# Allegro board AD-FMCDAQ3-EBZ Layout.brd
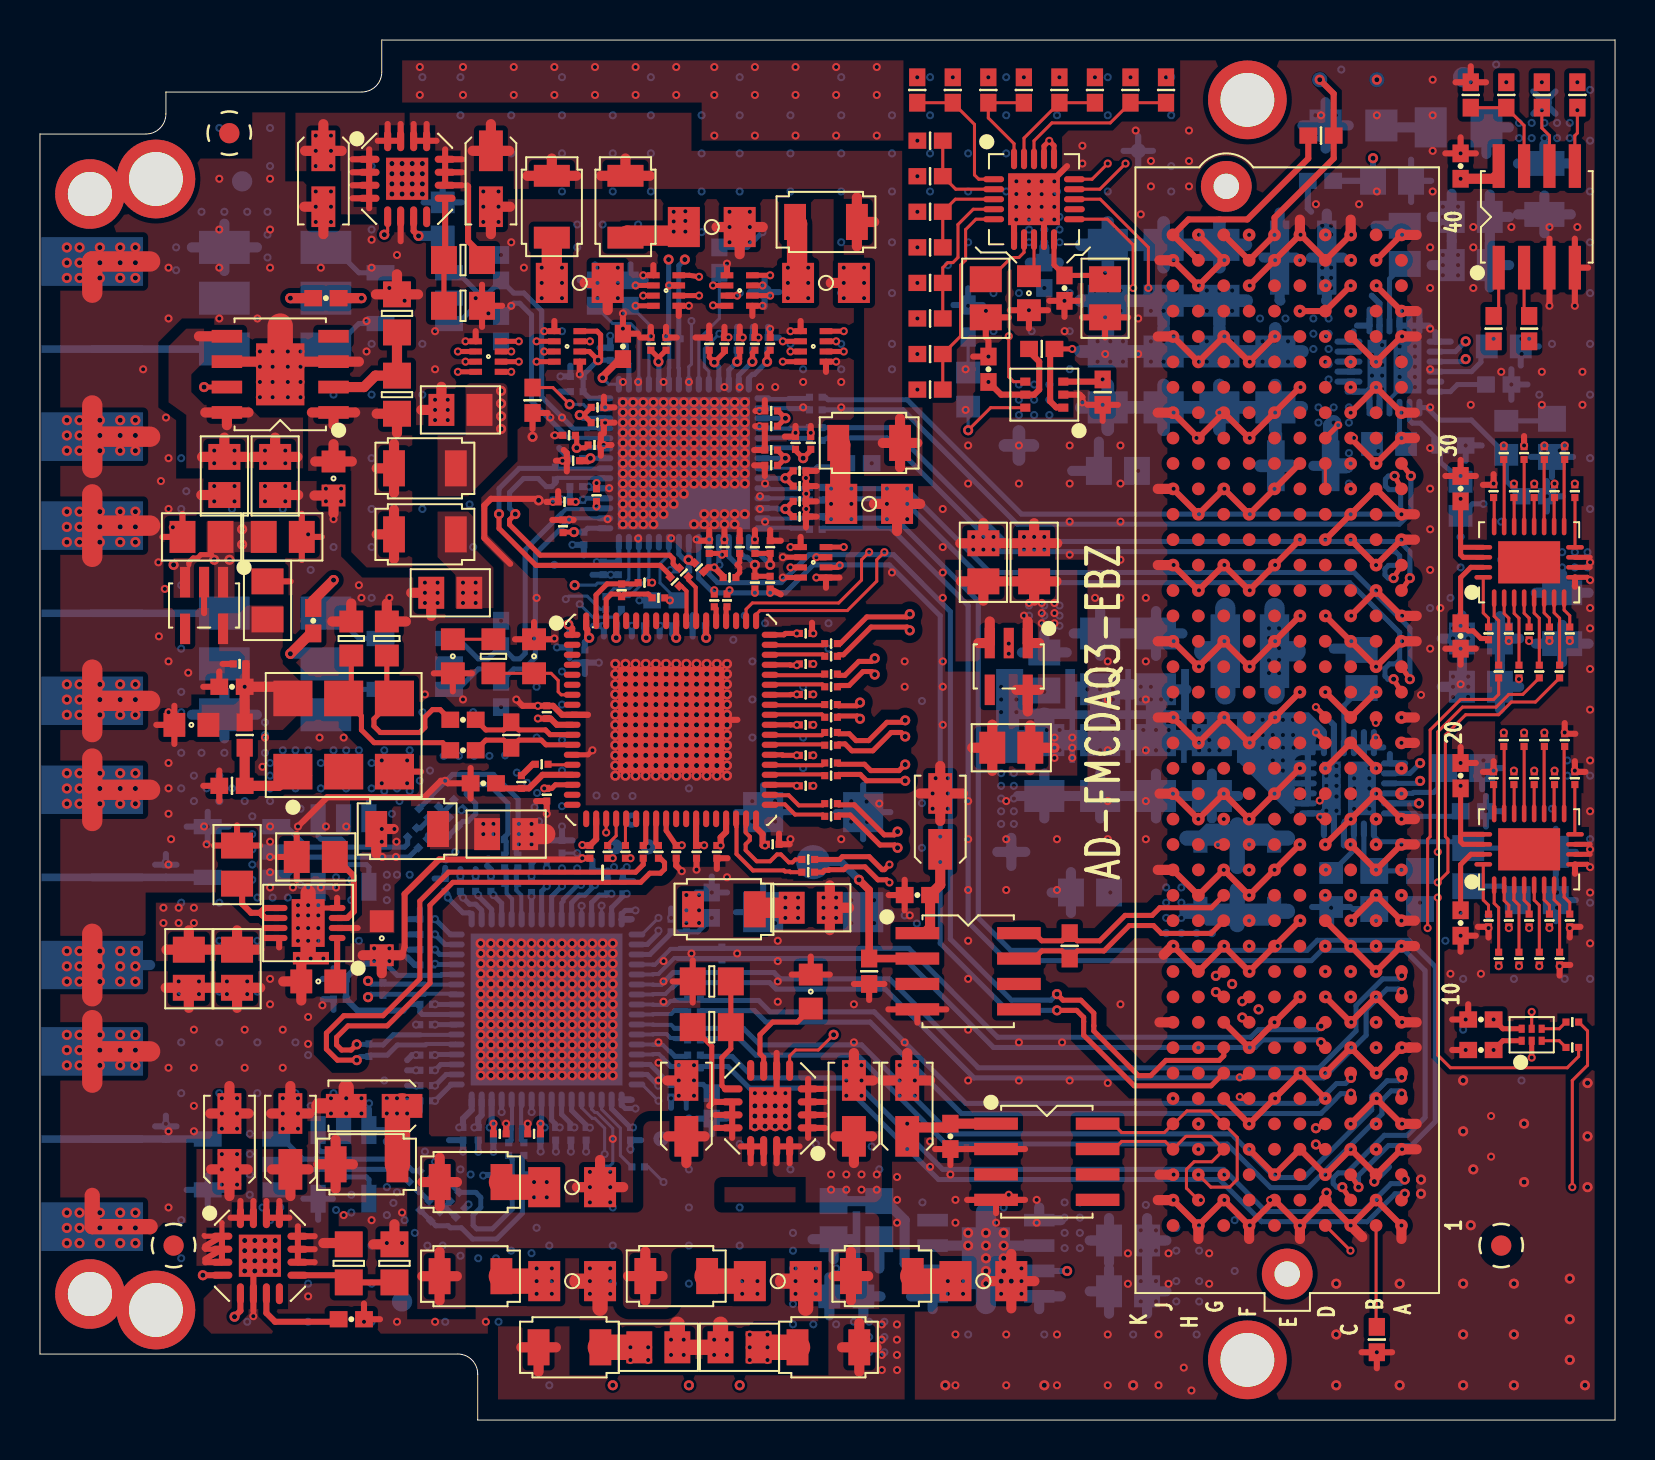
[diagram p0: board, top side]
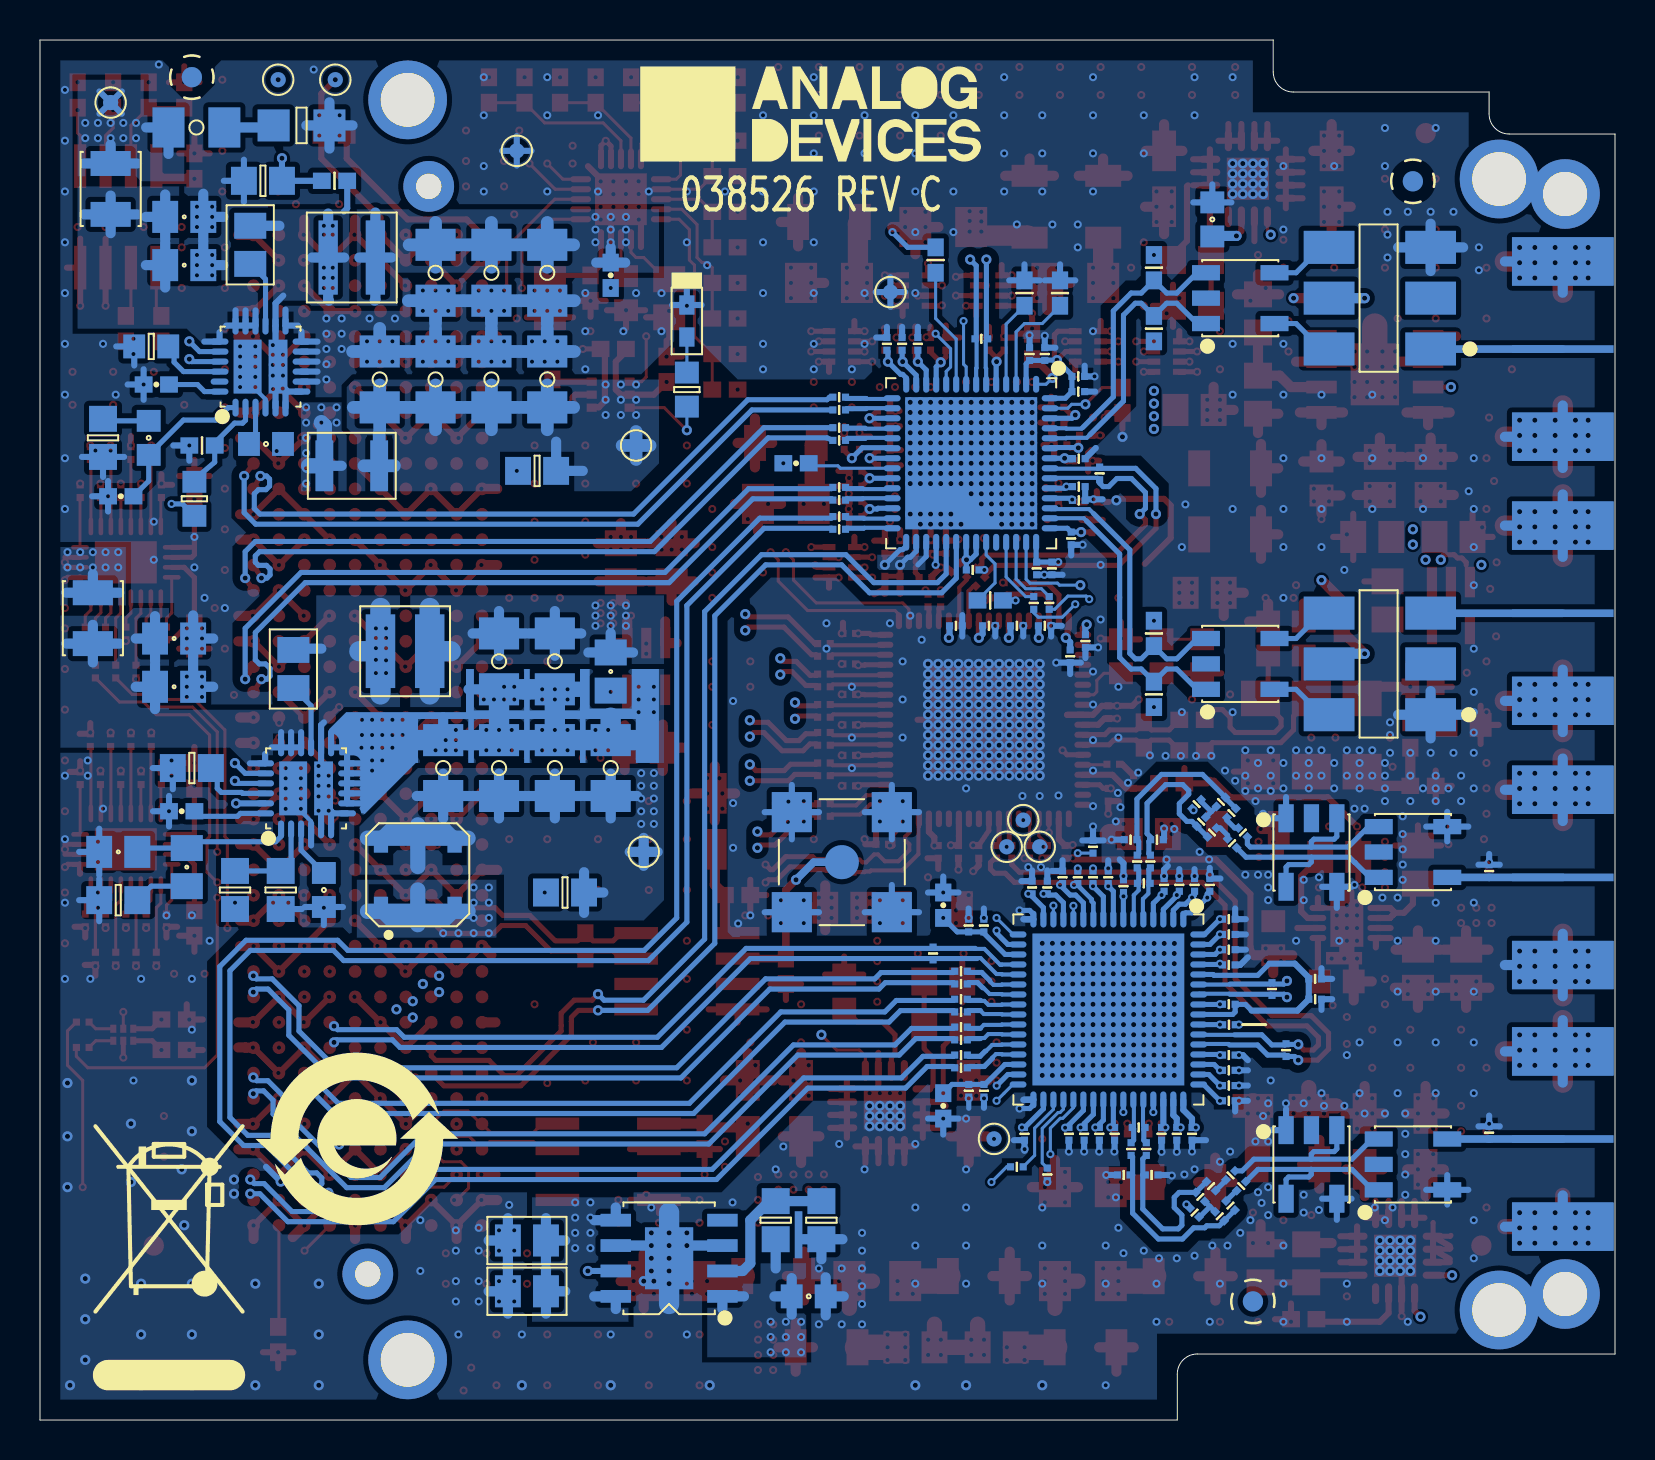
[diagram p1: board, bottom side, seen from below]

Outline 78.8 x 69 mm; copper layers: TOP, L2_AGND, L3_SIG, L4_AGND, L5_PWR, L6_PWR, L7_AGND, L8_SIG, L9_AGND, BOTTOM. Coordinates in mm from the lower left corner of the outline.
Outline path: 0,64.3 0,3.3 20.9,3.3 arc(21.61,3.01) 21.9,2.3 21.9,0 78.8,0 78.8,69 17.1,69 17.1,67.4 arc(16.81,66.69) 16.1,66.4 6.3,66.4 6.3,65.3 arc(6.01,64.59) 5.3,64.3 0,64.3

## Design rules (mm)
constraint set DEFAULT: min track width 0.152
net group ADC_CLK: nets ADC_CLK_N ADC_CLK_P
net group ADC_CLK1: nets ADC_CLK1_N ADC_CLK1_P
net group ADC_CLK_FMC: nets ADC_CLK_FMC_N ADC_CLK_FMC_P
net group ADC_CLK_FMC1: nets ADC_CLK_FMC1_N ADC_CLK_FMC1_P
net group ADC_SYNC: nets ADC_SYNC_N ADC_SYNC_P
net group ADC_SYSREF: nets ADC_SYSREF_N ADC_SYSREF_P
net group ADC_SYSREF1: nets ADC_SYSREF1_N ADC_SYSREF1_P
net group CLKD_SYSREF_ADC: nets CLKD_SYSREF_ADC_N CLKD_SYSREF_ADC_P
net group CLKD_SYSREF_ADC1: nets CLKD_SYSREF_ADC1_N CLKD_SYSREF_ADC1_P
net group CLKD_SYSREF_DAC: nets CLKD_SYSREF_DAC_N CLKD_SYSREF_DAC_P
net group CLKD_SYSREF_DAC1: nets CLKD_SYSREF_DAC1_N CLKD_SYSREF_DAC1_P
net group CLKEXT_TRIG: nets EXT_TRIG_N EXT_TRIG_P
net group CLKVINA: nets VINA_N VINA_P
net group CLKVINB: nets VINB_N VINB_P
net group DAC_CLK_FMC: nets DAC_CLK_FMC_N DAC_CLK_FMC_P
net group DAC_CLK_FMC1: nets DAC_CLK_FMC1_N DAC_CLK_FMC1_P
net group DAC_CLK_N: nets DAC_CLK1_N DAC_CLK_N
net group DAC_CLK_P: nets DAC_CLK1_P DAC_CLK_P
net group DAC_SYNC: nets DAC_SYNC_N DAC_SYNC_P
net group DAC_SYSREF: nets DAC_SYSREF_N DAC_SYSREF_P
net group DAC_SYSREF1: nets DAC_SYSREF1_N DAC_SYSREF1_P
net group DP2: nets UNNAMED_4_CAP_I87_N1 UNNAMED_4_CAP_I90_N1
net group DP3: nets UNNAMED_5_CAP_I52_N2 UNNAMED_5_CAP_I53_N2
net group DP4: nets UNNAMED_4_CAP_I87_N2 UNNAMED_4_CAP_I90_N2
net group DP6: nets UNNAMED_4_AD9528_I220_OUT3 UNNAMED_4_AD9528_I220_OUT3N
net group FMC_SERDIN0: nets DAC_SERDIN0_N DAC_SERDIN0_P
net group FMC_SERDIN0_A: nets FMC_SERDIN0_N FMC_SERDIN0_P
net group FMC_SERDIN1: nets DAC_SERDIN1_N DAC_SERDIN1_P
net group FMC_SERDIN1_A: nets FMC_SERDIN1_N FMC_SERDIN1_P
net group FMC_SERDIN2: nets DAC_SERDIN2_N DAC_SERDIN2_P
net group FMC_SERDIN2_A: nets FMC_SERDIN2_N FMC_SERDIN2_P
net group FMC_SERDIN3: nets DAC_SERDIN3_N DAC_SERDIN3_P
net group FMC_SERDIN3_A: nets FMC_SERDIN3_N FMC_SERDIN3_P
net group FMC_SERDOUT0: nets ADC_SERDOUT0_N ADC_SERDOUT0_P
net group FMC_SERDOUT0_A: nets FMC_SERDOUT0_N FMC_SERDOUT0_P
net group FMC_SERDOUT1: nets ADC_SERDOUT1_N ADC_SERDOUT1_P
net group FMC_SERDOUT1_A: nets FMC_SERDOUT1_N FMC_SERDOUT1_P
net group FMC_SERDOUT2: nets ADC_SERDOUT2_N ADC_SERDOUT2_P
net group FMC_SERDOUT2_A: nets FMC_SERDOUT2_N FMC_SERDOUT2_P
net group FMC_SERDOUT3: nets ADC_SERDOUT3_N ADC_SERDOUT3_P
net group FMC_SERDOUT3_A: nets FMC_SERDOUT3_N FMC_SERDOUT3_P
net group OUT0: nets OUT0_N OUT0_P
net group OUT1: nets OUT1_N OUT1_P
net group SYSREF: nets FMC_SYSREF_N FMC_SYSREF_P
net group SYSREF_A: nets FMC_SYSREF_N_A FMC_SYSREF_P_A
nets with their own width: min track width 0.254; nets 3P3_SUP ADC_1P2_AVDD ADC_1P2_AVDD_SR ADC_1P2_DRVDD ADC_1P2_DVDD ADC_2P5_AVDD ADC_3P3_AVDD ADC_3P3_SPIVDD DAC_1P2_CVDD12 DAC_1P2_DVDD12 DAC_1P2_PVDD12 DAC_1P2_SVDD12 DAC_3P3_AVDD33 DAC_3P3_IOVDD33 FMC_3P3V FMC_3P3VAUX FMC_12P0V
nets with their own width: min track width 0.508; nets P3V6

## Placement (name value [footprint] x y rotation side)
ADC_CSB  TESTPAD  [TPSMC30]  31.07 14.06 180 bottom
C1  0.1uF  [C0201]  31.76 41.92 135 top
C2  180pF  [C0603]  24.72 38.19 90 top
C3  0.1uF  [C0201]  32.21 42.38 135 top
C4  1uF  [C0603]  20.15 60.03 270 bottom
C5  0.047uF  [C0508IDC]  35.01 56.47 90 top
C6  0.001uF  [C0201]  35.67 53.81 270 bottom
C7  0.047uF  [C0508IDC]  31.32 56.47 270 top
C8  0.1uF  [C0201]  32.72 21.8 180 bottom
C9  0.047uF  [C0508IDC]  26.37 53.68 90 top
C10  0.047uF  [C0508IDC]  38.69 53.68 90 top
C11  0.1uF  [C0201]  39.58 34.38 0 top
C12  0.047uF  [C0508IDC]  38.69 42.88 270 top
C13  10uF  [C0603]  14.69 47.08 270 top
C14  0.1uF  [C0201]  39.58 37.3 0 top
C15  0.1uF  [C0201]  39.58 32.22 0 top
C16  0.1uF  [C0201]  39.58 33.74 0 top
C17  0.1uF  [C0201]  39.58 35.14 0 top
C18  1uF  [C0805H53]  54.44 6.44 0 bottom
C19  0.1uF  [C0201]  39.58 36.66 0 top
C20  0.1uF  [C0201]  32.72 22.44 180 bottom
C21  0.1uF  [C0201]  39.58 35.77 0 top
C22  0.1uF  [C0201]  35.77 53.81 270 top
C23  1uF  [C0805H53]  23.32 29.3 0 top
C24  1uF  [C0805H53]  38.56 25.61 0 top
C25  0.1uF  [C0402]  45.55 14.18 270 top
C26  0.001uF  [C0201]  38 45.93 180 top
C27  10uF  [C0603]  17.1 24.09 270 top
C28  0.1uF  [C0402]  43.9 26.25 180 top
C29  0.1uF  [C0201]  31.32 53.81 270 top
C30  0.1uF  [C0201]  28.53 39.71 0 bottom
C31  4.7uF  [C3216]  9.48 13.93 90 top
C32  0.1uF  [C0201]  32.97 39.71 0 bottom
C33  0.1uF  [C0201]  36.53 41.87 90 top
C34  1uF  [C0805H53]  11.77 47.2 270 top
C35  0.1uF  [C0201]  28.53 53.3 270 bottom
C36  0.001uF  [C0201]  36.58 47.74 0 top
C37  0.1uF  [C0201]  35.01 53.81 270 top
C38  0.001uF  [C0201]  26.83 46.67 0 bottom
C39  1uF  [C0402]  40.98 47.84 0 bottom
C40  0.1uF  [C0201]  30.94 28.41 270 top
C41  0.1uF  [C0201]  30.18 28.41 270 top
C42  0.1uF  [C0402]  14.31 56.09 180 top
C43  0.001uF  [C0201]  35.77 41.87 90 top
C44  0.1uF  [C0402]  13.67 39.96 270 top
C45  10uF  [C0603]  40.34 6.18 180 bottom
C46  0.1uF  [C0201]  27.89 50.63 180 top
C47  0.001uF  [C0201]  38 47.46 180 top
C48  1uF  [C0805H53]  9.23 47.2 270 top
C49  0.1uF  [C0201]  36.58 48.5 0 top
C50  0.1uF  [C0201]  38.56 48.85 270 top
C51  0.001uF  [C0201]  27.21 44.08 90 bottom
C52  0.1uF  [C0201]  36.58 49.69 0 top
C53  0.001uF  [C0201]  30.56 53.81 270 top
C54  0.001uF  [C0201]  37.8 48.85 270 top
C55  0.001uF  [C0201]  36.58 50.45 0 top
C56  0.001uF  [C0201]  36.43 53.81 270 bottom
C57  0.1uF  [C0201]  34.24 43.65 270 top
C58  0.001uF  [C0201]  33.48 43.65 270 top
C59  0.1uF  [C0201]  38.31 39.33 180 top
C60  0.1uF  [C0201]  26.5 38.95 90 bottom
C61  1uF  [C0603]  20.66 38.19 270 top
C62  0.001uF  [C0201]  24.08 31.9 90 top
C63  0.1uF  [C0201]  38.31 33.23 180 top
C64  0.1uF  [C0201]  27.51 28.41 90 top
C65  0.1uF  [C0201]  36.66 28.79 180 top
C66  0.1uF  [C0201]  38.31 31.71 180 top
C67  0.1uF  [C0402]  71.07 62.7 90 top
C68  4.7uF  [C3216]  43.39 15.58 90 top
C69  0.1uF  [C0402]  47.45 52.54 90 top
C70  0.1uF  [C0201]  31.83 28.41 90 top
C71  0.1uF  [C0201]  25.35 35.39 270 top
C72  0.1uF  [C0201]  32.85 28.41 90 top
C73  0.1uF  [C0201]  27.26 38.19 90 bottom
C74  390pF  [C0402]  21.16 35.01 0 top
C75  390pF  [C0402]  21.16 33.49 0 top
C76  4.7uF  [C3216]  45.04 29.93 90 top
C77  0.1uF  [C0201]  33.86 28.41 90 top
C78  0.1uF  [C0201]  29.93 39.71 0 bottom
C79  0.1uF  [C0201]  31.32 39.71 0 bottom
C80  0.1uF  [C0201]  38.31 37.8 180 top
C81  0.1uF  [C0201]  25.35 31.26 90 top
C82  0.1uF  [C0201]  38.31 36.28 180 top
C83  0.1uF  [C0201]  38.31 34.76 180 top
C84  0.1uF  [C0201]  32.72 20.41 180 bottom
C85  0.1uF  [C0201]  32.72 21.04 180 bottom
C86  0.1uF  [C0201]  32.72 19.01 180 bottom
C87  0.1uF  [C0201]  32.72 19.64 180 bottom
C88  0.1uF  [C0201]  32.72 17.61 180 bottom
C89  0.1uF  [C0402]  72.09 18.5 180 top
C90  0.1uF  [C0201]  27.84 46.24 90 top
C91  0.1uF  [C0402]  72.09 20.02 180 top
C92  0.1uF  [C0201]  32.72 18.25 180 bottom
C93  0.1uF  [C0201]  38.82 51.14 180 bottom
C94  0.1uF  [C0201]  35.77 43.65 270 top
C95  0.1uF  [C0201]  38.82 50.5 180 bottom
C96  4.7uF  [C3216]  16.72 15.71 180 top
C97  0.1uF  [C0201]  26.68 47.96 0 top
C98  0.1uF  [C0201]  32.97 42.63 135 top
C99  0.1uF  [C0201]  38.82 49.62 180 bottom
C100  0.1uF  [C0201]  26.12 28.66 90 bottom
C101  0.1uF  [C0201]  34.5 42.12 0 top
C102  0.1uF  [C0201]  38.82 48.98 180 bottom
C103  0.47uF  [C0402]  22.18 31.84 180 top
C104  0.001uF  [C0201]  29.29 53.3 270 bottom
C105  4pF  [C0201]  24.24 29.02 180 bottom
C106  1uF  [C0805H53]  12.15 44.15 0 top
C107  0.1uF  [C0201]  20.93 30.79 135 bottom
C108  0.1uF  [C0201]  18.62 29.38 45 bottom
C109  0.001uF  [C0201]  35.01 43.65 270 top
C110  0.1uF  [C0201]  38.82 46 180 bottom
C111  0.1uF  [C0201]  38.82 46.63 180 bottom
C112  1uF  [C0805H53]  8.08 44.15 180 top
C113  0.001uF  [C0201]  26.85 51.42 0 bottom
C114  0.001uF  [C0201]  32.14 42.5 0 bottom
C115  4pF  [C0201]  23.18 12.25 0 bottom
C116  4pF  [C0201]  24.58 12.25 0 bottom
C117  0.001uF  [C0201]  34.88 53.81 270 bottom
C118  0.1uF  [C0201]  19.24 12.23 315 bottom
C119  1uF  [C0805H53]  11.38 40.98 90 top
C120  0.1uF  [C0201]  26.85 52.18 0 bottom
C121  0.1uF  [C0201]  34.24 53.81 270 top
C122  0.1uF  [C0201]  36.53 53.81 270 top
C123  0.1uF  [C0201]  25.35 27.14 90 bottom
C124  0.1uF  [C0201]  38.82 44.54 180 bottom
C125  0.1uF  [C0201]  27.64 27.14 90 bottom
C126  0.01uF  [C0201]  9.99 37.8 180 top
C127  0.001uF  [C0201]  26.83 48.07 0 bottom
C128  0.001uF  [C0201]  33.48 53.81 270 top
C129  0.1uF  [C0201]  25.04 14.31 270 bottom
C130  0.1uF  [C0201]  22.69 14.31 270 bottom
C131  0.1uF  [C0201]  19.32 16.72 180 bottom
C132  0.1uF  [C0201]  38.82 45.17 180 bottom
C133  0.1uF  [C0201]  19.32 23.52 180 bottom
C134  0.1uF  [C0201]  19.32 24.28 180 bottom
C135  0.1uF  [C0201]  21.04 26.76 90 bottom
C136  0.1uF  [C0201]  21.93 14.31 270 bottom
C137  0.1uF  [C0201]  19.32 18.25 180 bottom
C138  0.1uF  [C0201]  19.32 19.76 180 bottom
C139  0.1uF  [C0201]  19.32 22.75 180 bottom
C140  0.1uF  [C0201]  22.56 26.76 90 bottom
C141  0.1uF  [C0201]  24.59 26.69 90 bottom
C142  0.1uF  [C0201]  24.72 14.31 180 top
C143  0.1uF  [C0201]  23 14.31 0 top
C144  0.1uF  [C0201]  20.27 26.76 90 bottom
C145  0.1uF  [C0201]  21.16 14.31 270 bottom
C146  0.1uF  [C0201]  19.32 15.96 180 bottom
C147  0.1uF  [C0201]  19.32 25.04 180 bottom
C148  0.001uF  [C0402]  15.58 5.04 0 top
C149  1uF  [C0805H53]  9.86 22.56 270 top
C150  0.1uF  [C0201]  28.4 26.63 90 bottom
C151  0.1uF  [C0201]  27.32 14.31 270 bottom
C152  1uF  [C0805H53]  54.44 8.98 0 bottom
C153  0.1uF  [C0201]  29.55 14.31 270 bottom
C154  0.1uF  [C0201]  19.32 20.79 180 bottom
C155  1uF  [C0402]  33.61 25.74 90 bottom
C156  0.1uF  [C0201]  26.17 44.69 270 top
C157  0.1uF  [C0201]  26.24 45.91 0 top
C158  0.001uF  [C0201]  26.83 45.98 0 bottom
C159  0.001uF  [C0201]  26.47 49.23 0 top
C160  0.1uF  [C0201]  27.74 48.75 180 top
C161  0.001uF  [C0201]  27.89 49.87 180 top
C162  0.1uF  [C0201]  39.58 38.19 0 top
C163  1uF  [C0805H53]  47.2 42.88 90 top
C164  1uF  [C0805H53]  21.04 50.5 180 top
C165  1uF  [C0805H53]  13.8 28.15 180 top
C166  1uF  [C0805H53]  7.45 22.56 270 top
C167  22uF  [C3216]  40.72 15.58 90 top
C168  0.1uF  [C0201]  39.58 38.82 0 top
C169  1uF  [C0603]  38.56 21.42 270 top
C170  22uF  [C3216]  32.34 15.58 90 top
C171  0.1uF  [C0201]  39.58 30.18 0 top
C172  0.1uF  [C0201]  39.58 32.85 0 top
C173  0.1uF  [C0201]  21.8 26.76 90 bottom
C174  0.1uF  [C0201]  39.58 30.82 0 top
C175  0.1uF  [C0201]  26.12 27.14 90 bottom
C176  0.1uF  [C0201]  26.88 27.14 90 bottom
C177  0.1uF  [C0201]  26.56 14.31 270 bottom
C178  10uF  [C0603]  13.92 21.93 180 top
C179  0.1uF  [C0201]  25.8 14.31 270 bottom
C180  1uF  [C0805H53]  20.53 41.36 180 top
C181  1uF  [C0805H53]  30.94 3.63 0 top
C182  4.7uF  [C3216]  12.53 13.93 90 top
C183  1uF  [C0805H53]  9.86 27.77 90 top
C184  10uF  [C0603]  7.57 34.76 180 top
C185  0.1uF  [C0201]  33.74 40.98 90 top
C186  22uF  [C3216]  14.18 62.06 270 top
C187  0.1uF  [C0201]  19.16 28.84 45 bottom
C188  0.1uF  [C0201]  18.7 11.69 315 bottom
C189  0.1uF  [C0201]  34.37 40.98 90 top
C190  0.1uF  [C0201]  21.04 10.37 225 bottom
C191  0.001uF  [C0201]  28.94 42.58 90 bottom
C192  0.1uF  [C0201]  28.17 42.58 90 bottom
C193  0.1uF  [C0201]  38.44 28.03 0 top
C194  0.1uF  [C0201]  38.44 27.39 0 top
C195  0.1uF  [C0201]  19.32 17.48 180 bottom
C196  2pF  [C0201]  23.58 26.83 0 bottom
C197  4pF  [C0201]  22.92 29.02 180 bottom
C198  2pF  [C0201]  23.83 14.63 180 bottom
C199  1uF  [C0402]  29.16 53.68 270 top
C204  0.1uF  [C0201]  38 45.17 180 top
C205  0.1uF  [C0201]  38 46.69 180 top
C206  0.001uF  [C0201]  36.53 43.65 270 top
C207  0.1uF  [C0201]  29.16 26.63 90 bottom
C208  1uF  [C0402]  33.61 15.71 270 bottom
C209  0.01uF  [C0201]  31.58 24.72 90 bottom
C210  0.01uF  [C0201]  31.57 16.46 270 bottom
C211  0.1uF  [C0201]  32.34 24.72 90 bottom
C212  0.1uF  [C0201]  32.33 16.46 270 bottom
C216  4.7uF  [C0603]  49.48 56.34 90 top
C217  0.1uF  [C0402]  51.26 56.59 90 top
C218  10uF  [C0805H53]  53.29 56.09 270 top
C219  10uF  [C0805H53]  47.32 56.09 90 top
C220  1uF  [C0805H53]  35 3.63 180 top
C222  22uF  [C3216]  22.56 62.06 270 top
C225  4.7uF  [C1206H71]  26.62 6.94 0 top
C226  4.7uF  [C1206H71]  26.62 11.64 0 top
C227  4.7uF  [C1206H71]  36.91 6.94 0 top
C228  4.7uF  [C1206H71]  33.61 59.65 0 top
C229  4.7uF  [C1206H71]  39.32 56.85 0 top
C230  4.7uF  [C1206H71]  41.48 45.81 0 top
C231  4.7uF  [C1206H71]  27.01 56.85 0 top
C232  4.7uF  [C1206H71]  47.2 6.94 0 top
C233  0.1uF  [C0402]  71.07 32.22 90 top
C234  0.1uF  [C0402]  71.07 46.57 90 top
C235  0.1uF  [C0402]  71.07 24.85 270 top
C236  0.1uF  [C0402]  71.07 39.2 270 top
C237  47uF  [C1206H71]  70.97 64.63 0 bottom
C261  1uF  [C0805H53]  48.6 33.61 180 top
C262  1uF  [C0805H53]  49.74 42.88 90 top
C535  0.1uF  [C0402]  9.61 36.66 0 top
CBST1  0.1uF  [C0805H53]  68.28 58.76 90 bottom
CBST2  0.1uF  [C0805H53]  66.12 37.55 90 bottom
CC0  0.001uF  [C0402]  74.76 46.19 0 bottom
CC1  0.027uF  [C0603]  73.36 49.11 90 bottom
CC02  100pF  [C0805]  74.88 28.41 180 bottom
CC12  0.033uF  [C0805]  71.46 27.64 90 bottom
CF1  47uF  [C1206]  59.01 57.36 90 bottom
CF2  47uF  [C1206]  56.22 57.36 90 bottom
CF3  47uF  [C1206]  53.42 57.36 90 bottom
CF4  47uF  [C1206H71]  55.83 37.93 90 bottom
CF5  47uF  [C1206H71]  53.04 37.93 90 bottom
CFB1  680pF  [C0402]  50.25 57.24 270 bottom
CFB2  100pF  [C0805]  50.25 37.42 90 bottom
CIN11  4.7uF  [C0805H60]  71.58 57.74 0 bottom
CIN12  4.7uF  [C0805H60]  72.09 39.07 0 bottom
CIN21  4.7uF  [C0805H60]  71.58 60.16 0 bottom
CIN22  4.7uF  [C0805H60]  72.09 36.66 0 bottom
CLKD_CSB  TESTPAD  [TPSMC30]  29.61 29.99 180 bottom
CN4  0.047uF  [C0508IDC]  22.43 53.17 270 top
CO1  47uF  [C1206]  61.8 52.03 270 bottom
CO2  47uF  [C1206]  59.01 52.03 270 bottom
CO3  47uF  [C1206]  56.22 52.03 270 bottom
CO4  47uF  [C1206]  53.42 52.03 270 bottom
CO5  47uF  [C1206H71]  58.63 32.6 270 bottom
CO6  47uF  [C1206H71]  55.83 32.6 270 bottom
CO7  47uF  [C1206H71]  53.04 32.6 270 bottom
CO8  47uF  [C1206H71]  50.25 32.6 270 bottom
CR1  LTST-C190GKT  [LED0603]  46.44 54.95 270 bottom
CSS1  TBD0402  [C0402]  72.98 51.77 180 bottom
CSS2  TBD0402  [C0402]  71.71 30.44 180 bottom
CVREG1  1uF  [C0603]  67.49 48.8 0 bottom
CVREG2  1uF  [C0603]  64.6 26.5 90 bottom
E1  65OHM AT 100MEGHZ  [L1210H59_HS]  21.54 7.19 0 top
E2  65OHM AT 100MEGHZ  [L1210H59_HS]  21.54 11.9 0 top
E3  65OHM AT 100MEGHZ  [L1210H59_HS]  31.83 7.2 0 top
E4  65OHM AT 100MEGHZ  [L1210H59_HS]  29.29 60.66 270 top
E5  65OHM AT 100MEGHZ  [L1210H59_HS]  39.32 59.9 180 top
E6  65OHM AT 100MEGHZ  [L1210H59_HS]  41.48 48.85 180 top
E7  65OHM AT 100MEGHZ  [L1210H59_HS]  25.61 60.66 270 top
E8  65OHM AT 100MEGHZ  [L1210H59_HS]  18.37 29.55 0 top
E9  65OHM AT 100MEGHZ  [L1210H59_HS]  42.12 7.2 0 top
E10  65OHM AT 100MEGHZ  [L1210H59_HS]  19.26 47.58 0 top
E11  65OHM AT 100MEGHZ  [L1210H59_HS]  34.22 25.54 0 top
E12  65OHM AT 100MEGHZ  [L1210H59_HS]  19.26 44.28 0 top
E17  65OHM AT 100MEGHZ  [L1210H59_HS]  16.34 12.79 0 top
E20  65OHM AT 100MEGHZ  [L1210H59_HS]  26.49 3.63 0 top
E21  65OHM AT 100MEGHZ  [L1210H59_HS]  39.44 3.63 180 top
GND  TESTPAD  [TPSMC30]  54.95 63.46 180 bottom
J1  R124.427.000  [CNSMASQ248H374]  38.68 27.89 180 bottom
JP3  0  [R0402]  71.58 66.25 270 top
L1  10uH  [LSMSQ157H161]  63.2 58.12 180 bottom
L10  1uH  [LSMSQ157H83]  60.53 38.44 180 bottom
L11  680nH  [LSML126W90H59]  63.2 47.71 180 bottom
L12  0.33UH  [LSMSQ154H47]  59.9 27.26 90 bottom
LIN1  0.47UH  [L1210H67]  75.27 61.55 270 bottom
LIN2  0.47UH  [L1210H67]  76.15 40.09 270 bottom
NOREF  -  []  104.25 69.01 0 top
NOREF#2  -  [unnamed#2]  9.47 64.34 0 top
NOREF#3  -  [unnamed#2]  2.5 61.3 0 top
NOREF#4  -  []  -191.31 -265.22 0 top
NOREF#5  -  [unnamed#2]  5.8 62.05 0 top
NOREF#6  -  [unnamed#2]  5.8 5.5 0 top
NOREF#7  -  []  78.8 107.22 0 top
NOREF#8  -  []  -166.32 200.43 0 top
NOREF#9  -  [unnamed#2]  73.11 8.72 0 top
NOREF#10  -  [unnamed#2]  2.5 6.3 0 top
NOREF#11  -  []  -193.34 -264.58 0 top
NOREF#12  -  []  21.59 3.02 0 top
NOREF#13  -  [unnamed#2]  60.41 3.01 0 top
NOREF#14  -  []  104.25 0.01 0 top
NOREF#15  -  [unnamed#2]  60.41 66.01 0 top
NOREF#16  -  []  -158.55 -78.79 0 top
NOREF#17  -  [unnamed#2]  6.69 8.72 0 top
NOREF#18  -  []  135.08 209.38 0 top
NOREF#19  -  []  41.8 77.59 0 top
NOREF#20  -  []  0 107.22 0 top
NOREF#21  -  []  -193.85 -261.79 0 top
NOREF#22  -  [unnamed#2]  10.11 61.93 180 bottom
NOREF#23  -  []  63.07 18.37 180 bottom
NOREF#24  -  [unnamed#2]  71.2 67.14 180 bottom
NOREF#25  -  []  40.21 65.3 180 bottom
NOREF#26  -  []  62.95 14.06 180 bottom
NOREF#27  -  [unnamed#2]  18.12 5.93 180 bottom
P501  ASP-134488-01  [CNSAMTECASP-134488-01]  62.4 34.49 90 top
R1  10K  [R0402]  9.61 31.71 180 top
R2  10.2K  [R0603]  22.69 38.19 90 top
R3  10K  [R0402]  64.06 61.96 0 bottom
R4  0  [R0201]  29.29 28.41 90 top
R5  100  [R0402]  23.58 34.25 270 top
R6  10K  [R0402]  10.24 34.25 270 top
R7  24.9K  [R0805]  66.76 26.5 90 bottom
R8  0  [R0402]  64.09 64.22 180 top
R9  49.9  [R0402]  41.48 22.44 270 top
R10  1K  [R0402]  72.73 54.57 90 top
R11  1K  [R0402]  74.5 54.57 90 top
R12  4.02K  [R0402]  47.45 66.5 90 top
R13  100  [R0201]  31.7 54.06 0 bottom
R14  100  [R0201]  25.79 47.33 90 bottom
R15  50  [R0402]  23.07 57.62 270 bottom
R16  1K  [R0402]  27.77 56.35 270 bottom
R17  4.02K  [R0402]  24.64 50.99 90 top
R18  1K  [R0402]  29.55 56.35 270 bottom
R19  1K  [R0402]  66.88 4.02 90 top
R20  1K  [R0402]  31.26 40.98 180 bottom
R21  38.3K  [R0805]  69.04 26.5 270 bottom
R22  50  [R0402]  23.07 54.57 270 bottom
R23  50  [R0402]  23.07 39.33 270 bottom
R24  4.02K  [R0402]  44.53 56.85 180 top
R25  50  [R0402]  23.07 36.28 270 bottom
R26  4.02K  [R0402]  44.53 55.08 0 top
R27  4.02K  [R0402]  44.53 53.3 180 top
R28  4.7K  [R0402]  75.14 66.25 270 top
R29  4.7K  [R0402]  73.36 66.25 270 top
R30  4.7K  [R0402]  76.92 66.25 270 top
R31  0  [R0201]  15 21.04 180 bottom
R32  10K  [R0402]  50.12 53.55 0 top
R33  10K  [R0402]  53.17 51.39 270 top
R34  150  [R0603]  46.44 51.52 90 bottom
R35  100  [R0402]  51.52 23.71 90 top
R36  4.02K  [R0402]  44.53 51.52 0 top
R37  29.4K  [R0805]  15.45 7.83 270 top
R38  7.32K  [R0805]  17.73 7.83 90 top
R39  4.02K  [R0402]  49.22 66.5 270 top
R40  4.02K  [R0402]  43.89 66.5 90 top
R41  33  [R0201]  73.49 24.98 90 top
R42  4.02K  [R0402]  45.67 66.5 270 top
R43  13K  [R0805]  17.86 55.33 270 top
R44  13K  [R0805]  39.71 9.99 90 bottom
R45  33  [R0201]  74.5 24.98 90 top
R46  0  [R0805]  17.86 51.27 270 top
R47  0  [R0805]  41.99 9.99 270 bottom
R48  200  [R0603]  17.35 39.07 90 top
R49  15K  [R0805]  33.61 19.64 180 top
R50  10K  [R0805]  33.61 21.93 0 top
R51  15K  [R0805]  21.16 58 0 top
R52  10K  [R0805]  21.16 55.71 180 top
R53  10  [R0201]  20.21 11.69 45 bottom
R54  10  [R0201]  19.24 10.72 225 bottom
R55  100  [R0201]  17.16 21.55 270 bottom
R56  100  [R0201]  16.46 18.49 270 bottom
R57  5K  [R0805]  67.65 61.96 0 bottom
R58  200  [R0603]  15.58 39.07 90 top
R59  4.02K  [R0402]  51 66.5 90 top
R60  4.02K  [R0402]  52.78 66.5 270 top
R61  4.02K  [R0402]  44.53 63.97 180 top
R62  4.02K  [R0402]  44.53 62.19 0 top
R63  4.02K  [R0402]  54.56 66.5 90 top
R64  4.02K  [R0402]  56.34 66.5 270 top
R65  10K  [R0201]  75.52 24.98 90 top
R66  6.34K  [R0402]  44.53 60.41 180 top
R67  1K  [R0402]  44.53 58.63 0 top
R68  0  [R0201]  15 22.06 180 bottom
R69  1  [R1206]  65.71 64.73 0 bottom
R70  10K  [R0201]  76.54 24.98 90 top
R71  33  [R0201]  75.01 23.07 90 top
R72  100  [R0201]  34.12 23.33 270 bottom
R73  10K  [R0201]  76.03 23.07 90 top
R74  33  [R0201]  72.98 23.07 90 top
R75  33  [R0201]  74 23.07 90 top
R76  33  [R0201]  73.74 32.09 90 top
R77  33  [R0201]  74.76 32.09 90 top
R78  33  [R0201]  75.27 33.99 90 top
R79  10K  [R0201]  72.47 24.98 270 top
R80  1K  [R0201]  72.73 32.09 270 top
R81  10K  [R0201]  76.28 33.99 270 top
R82  33  [R0201]  73.23 33.99 90 top
R83  0  [R0201]  25.1 32.79 0 top
R84  33  [R0201]  74.25 33.99 90 top
R85  10K  [R0201]  73.49 39.33 270 top
R86  33  [R0201]  74.5 39.33 90 top
R87  33  [R0201]  75.52 39.33 90 top
R88  33  [R0201]  76.54 39.33 90 top
R89  33  [R0201]  75.01 37.42 90 top
R90  33  [R0201]  76.03 37.42 90 top
R91  33  [R0201]  72.98 37.42 90 top
R92  10K  [R0201]  74 37.42 270 top
R93  10K  [R0201]  74.25 48.35 270 top
R94  33  [R0201]  74.76 46.44 90 top
R95  33  [R0201]  75.77 46.44 90 top
R96  33  [R0201]  76.79 46.44 90 top
R97  33  [R0201]  75.27 48.35 90 top
R98  33  [R0201]  76.28 48.35 90 top
R99  33  [R0201]  73.23 48.35 90 top
R100  10K  [R0201]  73.74 46.44 270 top
R101  0  [R0201]  28.4 28.41 90 top
R102  10  [R0201]  20.16 29.38 315 bottom
R103  10  [R0201]  19.19 30.35 135 bottom
R104  0  [R0201]  28.4 12.28 90 bottom
R105  0  [R0201]  29.93 12.66 180 bottom
R106  0  [R0201]  28.31 40.85 270 bottom
R107  0  [R0201]  29.08 40.85 270 bottom
R108  10  [R0201]  23.91 27.92 270 bottom
R109  10  [R0201]  23.25 27.92 270 bottom
R110  49.9  [R0201]  19.71 30.9 315 bottom
R111  49.9  [R0201]  20.7 29.92 315 bottom
R112  0  [R0201]  30.24 41.87 180 top
R113  0  [R0201]  30.94 41.11 180 top
R114  100  [R0201]  29.1 41.49 90 top
R115  33  [R0201]  76.66 18.63 180 top
R116  10K  [R0201]  75.77 32.09 270 top
R117  10K  [R0201]  76.79 32.09 270 top
R118  33  [R0201]  76.66 19.9 0 top
R119  10K  [R0201]  72.47 39.33 270 top
R120  1K  [R0201]  72.73 46.44 270 top
R121  49.9  [R0201]  6.3 27.45 90 bottom
R122  10K  [R0402]  33.99 58 90 bottom
R126  10  [R0201]  23.45 13.55 90 bottom
R127  10  [R0201]  24.21 13.55 90 bottom
R128  49.9  [R0201]  20.75 11.15 225 bottom
R129  49.9  [R0201]  19.78 10.18 225 bottom
R138  49.9  [R0201]  6.3 14.37 90 bottom
RC1  6.81K  [R0805]  75.65 49.11 90 bottom
RC12  3.16K  [R0805]  74.88 25.99 180 bottom
RF1  69.8K  [R0603]  71.07 46.06 270 bottom
RF2  13.7K  [R0402]  70.69 48.73 180 bottom
RFB1  5.23K  [R0805]  53.93 47.46 180 bottom
RFB2  4.02K  [R0805]  52.53 26.37 180 bottom
RT1  215K  [R0603]  73.23 53.68 0 bottom
RT22  76.8K  [R0805]  71.2 32.6 180 bottom
RX_A  JOHNSON142-0701-851  [CNJOHNSON142-0701-851]  2.61 27.13 180 bottom
RX_B  JOHNSON142-0701-851  [CNJOHNSON142-0701-851]  2.61 14.05 180 bottom
SCLK  TESTPAD  [TPSMC30]  28.78 28.66 180 bottom
SDIO  TESTPAD  [TPSMC30]  30.43 28.66 180 bottom
T1  ETC1-1-13  [ETC1]  18.75 37.8 90 bottom
T2  ETC1-1-13  [ETC1]  18.75 56.09 90 bottom
T3  ADT2-1T-1P+  [MINICD542]  11.77 56.09 90 bottom
T4  ADT2-1T-1P+  [MINICD542]  11.77 37.8 90 bottom
T100  ETC1-1-13  [ETC1]  15.19 28.37 180 bottom
T101  ETC1-1-13  [ETC1]  10.11 28.4 90 bottom
T102  ETC1-1-13  [ETC1]  15.19 12.78 180 bottom
T103  ETC1-1-13  [ETC1]  10.11 12.78 90 bottom
TP1  TESTPAD  [TPSMC30]  36.25 56.4 180 bottom
TP2  TESTPAD  [TPSMC30]  48.98 48.73 270 bottom
TP3  TESTPAD  [TPSMC30]  48.6 28.41 90 bottom
TX_A  JOHNSON142-0701-851  [CNJOHNSON142-0701-851]  2.61 53.55 180 bottom
TX_B  JOHNSON142-0701-851  [CNJOHNSON142-0701-851]  2.61 40.34 180 bottom
U1  AD9152  [QFN56_8X8_PAD6_6X6_6]  32.21 47.84 0 bottom
U2  M24C02-RMN6TP  [SO8]  74.88 60.16 0 top
U3  ADP2384ACPZN  [QFN24_4X4_2PAD]  65.49 31.58 180 bottom
U4  NC7WZ16P6X  [SC70]  50.25 51.27 90 top
U5  ADP1755ACPZ  [QFN16_4X4_PAD2_1X2_1]  11 8.21 270 top
U6  ADP2384ACPZN  [QFN24_4X4_2PAD]  67.77 52.67 180 bottom
U7  AD9528BCPZ  [QFN72_10X10_PAD5_3X5_3]  31.58 35.01 270 top
U8  ADM7154ACPZ-3.3  [DFN8_3X3_PAD2_38X1_64]  13.42 24.85 90 top
U9  FXLH1T45L6X  [PSON6]  74.63 19.26 0 top
U10  ADP7104ARDZ-3.3  [SO8NB-PAD3_1X2_41]  12.02 52.28 90 top
U11  ADP7104ARDZ-3.3  [SO8NB-PAD3_1X2_41]  47.33 8.09 90 bottom
U12  FXL4245MPX  [MLP24_4_5X3_5_PAD3_1X2_1]  74.5 42.88 0 top
U13  FXL4245MPX  [MLP24_4_5X3_5_PAD3_1X2_1]  74.5 28.53 0 top
U14  ADN4661BRZ  [SO8]  50.37 12.91 270 top
U15  ADN4661BRZ  [SO8]  46.44 22.44 270 top
U16  ADP150AUJZ-3.3-R7  [TSOT-5]  8.21 40.73 180 top
U17  ADP1741ACPZ  [QFN16_4X4_PAD2_1X2_1]  36.53 15.58 90 top
U18  AD7291BCPZ  [QFN20_4X4_PAD2_6X2_6]  49.73 61.04 270 top
U19  ADP1741ACPZ  [QFN16_4X4_PAD2_1X2_1]  18.37 62.06 270 top
U22  ADP150AUJZ-3.3-R7  [TSOT-5]  48.47 37.68 180 top
U100  AD9680BCPZ-1000  [QFN64_9X9_PAD7_6X7_6]  25.35 20.53 0 bottom
UNK3P3V  TESTPAD  [TPSMC30]  66.88 67.01 180 bottom
UNK12P0V  TESTPAD  [TPSMC30]  75.27 65.87 180 bottom
VADJ  TESTPAD  [TPSMC30]  64.03 67.01 180 bottom
Y1  100MEGHZ  [YSML276W197H63]  15.19 34.25 0 top

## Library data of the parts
ADC_CSB CLKD_CSB GND SCLK SDIO TP1-TP3 UNK3P3V UNK12P0V VADJ = NCTESTPAD: Tolerance: N/A; User Part Number: UPN; alternate symbols: (); part number: NCTESTPAD_SM-TESTPAD,E012884,TPSMC30; tolerance: N/A
C1 C3 = CAP: alternate symbols: (); part number: CAP_SM-0.1UF,6.3V,10,E011567,C0201; tolerance: 10; signal model: capacitor20pF
C2 = CAP: Tolerance: 5; User Part Number: UPN; alternate symbols: (); part number: CAP_SM-180PF,50V,5,E012698,C0603; tolerance: 5
C4 C61 C169 CVREG1 CVREG2 = CAP: Tolerance: 10; User Part Number: UPN; alternate symbols: (); part number: CAP_SM-1UF,16V,10,E006882,C0603; tolerance: 10
C5 C7 C9 C10 C12 CN4 = CAPARRAY8PP: Tolerance: N/A; User Part Number: UPN; alternate symbols: (); part number: CAPARRAY8PP_SM-0.047UF,N/A,N/A,E007353,C0508IDC; tolerance: N/A
C6 C26 C36 C38 C43 C47 C51 C53-C56 C58 C62 C104 C109 C113 C114 C117 C127 C128 C158 C159 C161 C191 C206 = CAP: alternate symbols: (); part number: CAP_SM-0.001UF,25V,10,E006762,C0201; tolerance: 10
C8 C11 C14-C17 C19-C22 C29 C30 C32 C33 C35 C37 C40 C41 C46 C49 C50 C52 C57 C59 C60 C63-C66 C70-C73 C77-C88 C90 C92-C95 C97-C99 C101 C102 C107 C110 C111 C120-C125 C129-C147 C150 C151 C153 C154 C156 C157 C160 C162 C168 C171-C177 C179 C185 C189 C190 C192-C195 C204 C205 C207 C211 C212 = CAP: alternate symbols: (); part number: CAP_SM-0.1UF,6.3V,10,E011567,C0201; tolerance: 10
C13 C27 C45 C178 C184 = CAP: Tolerance: 20; User Part Number: UPN; alternate symbols: (); part number: CAP_SM-10UF,6.3V,20,E007143,C0603; tolerance: 20
C18 C23 C24 C34 C48 C106 C112 C119 C149 C152 C163-C166 C180 C181 C183 C220 C261 C262 = CAP: Tolerance: 10; User Part Number: UPN; alternate symbols: (); part number: CAP_SM-1UF,16V,10,E011046,C0805H53; tolerance: 10
C25 C28 C42 C44 C67 C69 C89 C91 C217 C233-C236 C535 = CAP: Tolerance: 10; User Part Number: UPN; alternate symbols: (); part number: CAP_SM-0.1UF,16V,10,E007200,C0402; tolerance: 10
C31 C68 C76 C96 C182 = CAPP: Tolerance: N/A; User Part Number: UPN; alternate symbols: (); part number: CAPP_SM-4.7UF,N/A,N/A,E000691,C3216; tolerance: N/A
C39 C199 = CAP: Tolerance: 10; User Part Number: UPN; alternate symbols: (); part number: CAP_SM-1UF,6.3V,10,E011561,C0402; tolerance: 10
C74 C75 = CAP: Tolerance: 5; User Part Number: UPN; alternate symbols: (); part number: CAP_SM-390PF,50V,5,E013656,C0402; tolerance: 5
C100 C108 C118 C187 C188 = CAP: alternate symbols: (); part number: CAP_SM-0.1UF,16V,20,E017331,C0201; tolerance: 20
C103 = CAP: Tolerance: 10; User Part Number: UPN; alternate symbols: (); part number: CAP_SM-0.47UF,10V,10,E007611,C0402; tolerance: 10
C105 C115 C116 C197 = CAP: alternate symbols: (); part number: CAP_SM-4PF,25V,0.1PF,E020387,C0201; tolerance: 0.1pF
C126 C209 C210 = CAP: alternate symbols: (); part number: CAP_SM-0.01UF,10V,10,E007201,C0201; tolerance: 10
C148 = CAP: Tolerance: 10; User Part Number: UPN; alternate symbols: (); part number: CAP_SM-0.001UF,50V,10,E006276,C0402; tolerance: 10
C155 C208 = CAP: Tolerance: 10; User Part Number: UPN; alternate symbols: (); part number: CAP_SM-1UF,6.3V,10,E007449,C0402; tolerance: 10
C167 C170 C186 C222 = CAPP: Tolerance: N/A; User Part Number: UPN; alternate symbols: (); part number: CAPP_SM-22UF,N/A,N/A,E000683,C3216; tolerance: N/A
C196 C198 = CAP: alternate symbols: (); part number: CAP_SM-2PF,25V,0.1PF,E020386,C0201; tolerance: 0.1pF
C216 = CAP: Tolerance: 10; User Part Number: UPN; alternate symbols: (); part number: CAP_SM-4.7UF,6.3V,10,E010382,C0603; tolerance: 10
C218 C219 = CAP: Tolerance: 10; User Part Number: UPN; alternate symbols: (); part number: CAP_SM-10UF,16V,10,E006166,C0805H53; tolerance: 10
C225-C232 = CAP: Tolerance: 5; User Part Number: UPN; alternate symbols: (); part number: CAP_SM-4.7UF,25V,5,E018908,C1206H71; tolerance: 5
C237 = CAP: Tolerance: 20; User Part Number: UPN; alternate symbols: (); part number: CAP_SM-47UF,16V,20,E019684,C1206H71; tolerance: 20
CBST1 CBST2 = CAP: Tolerance: 10; User Part Number: UPN; alternate symbols: (); part number: CAP_SM-0.1UF,50V,10,E010137,C0805H53; tolerance: 10
CC0 = CAP: Tolerance: 5; User Part Number: UPN; alternate symbols: (); part number: CAP_SM-0.001UF,25V,5,E017843,C0402; tolerance: 5
CC1 = CAP: Tolerance: 10; User Part Number: UPN; alternate symbols: (); part number: CAP_SM-0.027UF,50V,10,E005339,C0603; tolerance: 10
CC02 CFB2 = CAP: Tolerance: 5; User Part Number: UPN; alternate symbols: (); part number: CAP_SM-100PF,100V,5,E000465,C0805; tolerance: 5
CC12 = CAP: Tolerance: 5; User Part Number: UPN; alternate symbols: (); part number: CAP_SM-0.033UF,50V,5,E005162,C0805; tolerance: 5
CF1-CF3 CO1-CO4 = CAP: Tolerance: 20; User Part Number: UPN; alternate symbols: (); part number: CAP_SM-47UF,6.3V,20,E006154,C1206; tolerance: 20
CF4 CF5 CO5-CO8 = CAP: Tolerance: 20; User Part Number: UPN; alternate symbols: (); part number: CAP_SM-47UF,10V,20,E020003,C1206H71; tolerance: 20
CFB1 = CAP: Tolerance: 5; User Part Number: UPN; alternate symbols: (); part number: CAP_SM-680PF,50V,5,E007981,C0402; tolerance: 5
CIN11 CIN12 CIN21 CIN22 = CAP: Tolerance: 20; User Part Number: UPN; alternate symbols: (); part number: CAP_SM-4.7UF,25V,20,E020124,C0805H60; tolerance: 20
CR1 = DIOLED: Tolerance: N/A; User Part Number: UPN; alternate symbols: (); part number: DIOLED_SM-LTST-C190GKT,N/A,N/A,E006239,LED0603; tolerance: N/A
CSS1 CSS2 = CAP: User Part Number: UPN; alternate symbols: (); part number: CAP_SM-TBD0402,TBD0402,TBD0402,E000381,C0402
E1-E12 E17 E20 E21 = FERRITE: User Part Number: UPN; Tolerance: 25; alternate symbols: (); part number: FERRITE_SM-65OHM AT 100MEGHZ,25,E021914,L1210H59_HS; tolerance: 25
J1 = CNBNC5P: Tolerance: N/A; User Part Number: UPN; alternate symbols: (); part number: CNBNC5P_SM-R124.427.000,E012757,CNSMASQ248H374; tolerance: N/A
JP3 = RES: Tolerance: 1; User Part Number: UPN; alternate symbols: (); part number: RES_SM-0,E010661,1/16W,1,R0402; tolerance: 1
L1 = IND: User Part Number: UPN; Tolerance: 20; alternate symbols: (); part number: IND_SM-10UH,20,E016513,LSMSQ157H161; tolerance: 20
L10 = IND: User Part Number: UPN; Tolerance: 20; alternate symbols: (); part number: IND_SM-1UH,20,E015845,LSMSQ157H83; tolerance: 20
L11 = IND: User Part Number: UPN; Tolerance: 20; alternate symbols: (); part number: IND_SM-680NH,20,E020008,LSML126W90H59; tolerance: 20
L12 = IND: Tolerance: 20; User Part Number: UPN; alternate symbols: (); part number: IND_SM-0.33UH,20,E018628,LSMSQ154H47; tolerance: 20
LIN1 LIN2 = IND: User Part Number: UPN; Tolerance: 30; alternate symbols: (); part number: IND_SM-0.47UH,30,E018627,L1210H67; tolerance: 30
P501 = CN400P_A_K_V2: User Part Number: UPN; Tolerance: N/A; alternate symbols: (); part number: CN400P_A_K_V2_SM-ASP-134488-01,E011384,CNSAMTECASP-134488-01; tolerance: N/A
R1 R3 R6 R32 R33 R122 = RES: Tolerance: 1; User Part Number: UPN; alternate symbols: (); part number: RES_SM-10K,E003751,1/10W,1,R0402; tolerance: 1
R2 = RES: Tolerance: 1; User Part Number: UPN; alternate symbols: (); part number: RES_SM-10.2K,E013703,1/10W,1,R0603; tolerance: 1
R4 R31 R68 R83 R101 R104-R107 R112 R113 = RES: Tolerance: 5; User Part Number: UPN; alternate symbols: (); part number: RES_SM-0,E004015,1/20W,5,R0201; tolerance: 5
R5 R35 = RES: Tolerance: 1; User Part Number: UPN; alternate symbols: (); part number: RES_SM-100,E003760,1/16W,1,R0402; tolerance: 1
R7 = RES: Tolerance: 1; User Part Number: UPN; alternate symbols: (); part number: RES_SM-24.9K,E003485,1/8W,1,R0805; tolerance: 1
R8 = RES: Tolerance: 5; User Part Number: UPN; alternate symbols: (); part number: RES_SM-0,E003438,N/A,5,R0402; tolerance: 5
R9 = RES: Tolerance: 1; User Part Number: UPN; alternate symbols: (); part number: RES_SM-49.9,E003750,1/16W,1,R0402; tolerance: 1
R10 R11 R16 R18-R20 R67 = RES: Tolerance: 1; User Part Number: UPN; alternate symbols: (); part number: RES_SM-1K,E003763,1/10W,1,R0402; tolerance: 1
R12 R17 R24 R26 R27 R36 R39 R40 R42 R59-R64 = RES: Tolerance: 1; User Part Number: UPN; alternate symbols: (); part number: RES_SM-4.02K,E004026,1/16W,1,R0402; tolerance: 1
R13 R14 R55 R56 R72 R114 = RES: Tolerance: 1; User Part Number: UPN; alternate symbols: (); part number: RES_SM-100,E007239,1/20W,1,R0201; tolerance: 1
R15 R22 R23 R25 = RES: Tolerance: 0.1; User Part Number: UPN; alternate symbols: (); part number: RES_SM-50,E016309,1/20W,0.1,R0402; tolerance: 0.1
R21 = RES: Tolerance: 1; User Part Number: UPN; alternate symbols: (); part number: RES_SM-38.3K,E020004,1/8W,1,R0805; tolerance: 1
R28-R30 = RES: Tolerance: 1; User Part Number: UPN; alternate symbols: (); part number: RES_SM-4.7K,E008190,1/10W,1,R0402; tolerance: 1
R34 = RES: Tolerance: 0.1; User Part Number: UPN; alternate symbols: (); part number: RES_SM-150,E013609,1/10W,0.1,R0603; tolerance: 0.1
R37 = RES: Tolerance: 1; User Part Number: UPN; alternate symbols: (); part number: RES_SM-29.4K,E018575,1/8W,1,R0805; tolerance: 1
R38 = RES: Tolerance: 1; User Part Number: UPN; alternate symbols: (); part number: RES_SM-7.32K,E003544,1/8W,1,R0805; tolerance: 1
R41 R45 R71 R74-R78 R82 R84 R86-R91 R94-R99 R115 R118 = RES: Tolerance: 1; User Part Number: UPN; alternate symbols: (); part number: RES_SM-33,E011241,1/20W,1,R0201; tolerance: 1
R43 R44 = RES: Tolerance: 1; User Part Number: UPN; alternate symbols: (); part number: RES_SM-13K,E003507,1/8W,1,R0805; tolerance: 1
R46 R47 = RES: Tolerance: N/A; User Part Number: UPN; alternate symbols: (); part number: RES_SM-0,E004449,1/8W,N/A,R0805; tolerance: N/A
R48 R58 = RES: Tolerance: 1; User Part Number: UPN; alternate symbols: (); part number: RES_SM-200,E007248,1/10W,1,R0603; tolerance: 1
R49 R51 = RES: Tolerance: 1; User Part Number: UPN; alternate symbols: (); part number: RES_SM-15K,E004159,1/10W,1,R0805; tolerance: 1
R50 R52 = RES: Tolerance: 1; User Part Number: UPN; alternate symbols: (); part number: RES_SM-10K,E003254,1/8W,1,R0805; tolerance: 1
R53 R54 R102 R103 R108 R109 R126 R127 = RES: Tolerance: 1; User Part Number: UPN; alternate symbols: (); part number: RES_SM-10,E013982,1/20W,1,R0201; tolerance: 1
R57 = RES: Tolerance: 0.1; User Part Number: UPN; alternate symbols: (); part number: RES_SM-5K,E014315,1/5W,0.1,R0805; tolerance: 0.1
R65 R70 R73 R79 R81 R85 R92 R93 R100 R116 R117 R119 = RES: Tolerance: 1; User Part Number: UPN; alternate symbols: (); part number: RES_SM-10K,E004011,1/20W,1,R0201; tolerance: 1
R66 = RES: Tolerance: 1; User Part Number: UPN; alternate symbols: (); part number: RES_SM-6.34K,E003777,1/16W,1,R0402; tolerance: 1
R69 = RES: User Part Number: UPN; alternate symbols: (); part number: RES_SM-1,E014141,1/4W,1,R1206
R80 R120 = RES: Tolerance: 1; User Part Number: UPN; alternate symbols: (); part number: RES_SM-1K,E004010,1/20W,1,R0201; tolerance: 1
R110 R111 R121 R128 R129 R138 = RES: Tolerance: 1; User Part Number: UPN; alternate symbols: (); part number: RES_SM-49.9,E007693,1/20W,1,R0201; tolerance: 1
RC1 = RES: Tolerance: 0.1; User Part Number: UPN; alternate symbols: (); part number: RES_SM-6.81K,E010999,1/8W,0.1,R0805; tolerance: 0.1
RC12 = RES: Tolerance: 0.1; User Part Number: UPN; alternate symbols: (); part number: RES_SM-3.16K,E010883,1/10W,0.1,R0805; tolerance: 0.1
RF1 = RES: Tolerance: 1; User Part Number: UPN; alternate symbols: (); part number: RES_SM-69.8K,E010277,1/10W,1,R0603; tolerance: 1
RF2 = RES: Tolerance: 1; User Part Number: UPN; alternate symbols: (); part number: RES_SM-13.7K,E019610,1/16W,1,R0402; tolerance: 1
RFB1 = RES: Tolerance: 1; User Part Number: UPN; alternate symbols: (); part number: RES_SM-5.23K,E004041,1/8W,1,R0805; tolerance: 1
RFB2 = RES: Tolerance: 1; User Part Number: UPN; alternate symbols: (); part number: RES_SM-4.02K,E003522,1/8W,1,R0805; tolerance: 1
RT1 = RES: Tolerance: 1; User Part Number: UPN; alternate symbols: (); part number: RES_SM-215K,E011041,1/10W,1,R0603; tolerance: 1
RT22 = RES: Tolerance: 1; User Part Number: UPN; alternate symbols: (); part number: RES_SM-76.8K,E014296,1/8W,1,R0805; tolerance: 1
RX_A RX_B TX_A TX_B = CNBNC5P: Tolerance: N/A; User Part Number: UPN; alternate symbols: (); part number: CNBNC5P_SM-JOHNSON142-0701-851,E000923,CNJOHNSON142-0701-851; tolerance: N/A
T1 T2 T100-T103 = XFMRETC1: Tolerance: N/A; User Part Number: UPN; alternate symbols: (); part number: XFMRETC1_SM-ETC1-1-13,E004586,ETC1; tolerance: N/A
T3 T4 = XFMRMCCD542KS: Tolerance: N/A; User Part Number: UPN; alternate symbols: (); part number: XFMRMCCD542KS_SM-ADT2-1T-1P+,E007172,MINICD542; tolerance: N/A
U1 = AD9152: User Part Number: UPN; Tolerance: N/A; alternate symbols: (); part number: AD9152_SM-AD9152,E019568,QFN56_8X8_PAD6_6X6_6; tolerance: N/A
U2 = ICM24CXX: Tolerance: N/A; User Part Number: UPN; alternate symbols: (); part number: ICM24CXX_SM-M24C02-RMN6TP,E018349,SO8; tolerance: N/A
U3 U6 = ADP238X: User Part Number: UPN; Tolerance: N/A; alternate symbols: (); part number: ADP238X_SM-ADP2384ACPZN,E012984,QFN24_4X4_2PAD; tolerance: N/A
U4 = NC7WZ17P6X: Tolerance: N/A; User Part Number: UPN; alternate symbols: (); part number: NC7WZ17P6X_SM-NC7WZ16P6X,E002060,SC70; tolerance: N/A
U5 = ADP1755: Tolerance: N/A; User Part Number: UPN; alternate symbols: (); part number: ADP1755_SM-ADP1755ACPZ,E012964,QFN16_4X4_PAD2_1X2_1; tolerance: N/A
U7 = AD9528: User Part Number: UPN; Tolerance: N/A; alternate symbols: (); part number: AD9528_SM-AD9528BCPZ,E019427,QFN72_10X10_PAD5_3X5_3; tolerance: N/A
U8 = ADM7154: Tolerance: N/A; User Part Number: UPN; alternate symbols: (); part number: ADM7154_SM-ADM7154ACPZ-3.3,E020267,DFN8_3X3_PAD2_38X1_64; tolerance: N/A
U9 = ICFXLH1T45: User Part Number: UPN; Tolerance: N/A; alternate symbols: (); part number: ICFXLH1T45_SM-FXLH1T45L6X,E021618,PSON6; tolerance: N/A
U10 U11 = ADP7104: Tolerance: N/A; User Part Number: UPN; alternate symbols: (); part number: ADP7104_SM-ADP7104ARDZ-3.3,E016463,SO8NB-PAD3_1X2_41; tolerance: N/A
U12 U13 = ICFXL4245: Tolerance: N/A; User Part Number: UPN; alternate symbols: (); part number: ICFXL4245_SM-FXL4245MPX,E014925,MLP24_4_5X3_5_PAD3_1X2_1; tolerance: N/A
U14 U15 = ADN4661: Tolerance: N/A; User Part Number: UPN; alternate symbols: (); part number: ADN4661_SM-ADN4661BRZ,E013548,SO8; tolerance: N/A
U16 U22 = ADP120_V2: User Part Number: UPN; Tolerance: N/A; alternate symbols: (); part number: ADP120_V2_SM-ADP150AUJZ-3.3-R7,E011418,TSOT-5; tolerance: N/A
U17 U19 = ADP1741: Tolerance: N/A; User Part Number: UPN; alternate symbols: (); part number: ADP1741_SM-ADP1741ACPZ,E014231,QFN16_4X4_PAD2_1X2_1; tolerance: N/A
U18 = AD7291: User Part Number: UPN; Tolerance: N/A; alternate symbols: (); part number: AD7291_SM-AD7291BCPZ,E017361,QFN20_4X4_PAD2_6X2_6; tolerance: N/A
U100 = AD9680: User Part Number: UPN; Tolerance: N/A; alternate symbols: (); part number: AD9680_SM-AD9680BCPZ-1000,E017636,QFN64_9X9_PAD7_6X7_6; tolerance: N/A
Y1 = XTALOSC6P_V15: User Part Number: UPN; Tolerance: N/A; alternate symbols: (); part number: XTALOSC6P_V15_SM-100MEGHZ,E029015,YSML276W197H63; tolerance: N/A

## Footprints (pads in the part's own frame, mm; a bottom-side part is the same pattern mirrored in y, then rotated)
C0201
  rect 0.356x0.356 smd: 1(-0.318,0) 2(0.318,0)
C0402
  rect 0.889x0.813 smd: 1(-0.635,0) 2(0.635,0)
C0508IDC
  rect 0.305x0.635 smd: 1(-0.762,-0.635) 2(-0.254,-0.635) 3(0.254,-0.635) 4(0.762,-0.635) 5(0.762,0.635) 6(0.254,0.635) 7(-0.254,0.635) 8(-0.762,0.635)
C0603
  rect 1.092x1.194 smd: 1(-0.851,0) 2(0.851,0)
C0805
  rect 1.295x1.6 smd: 1(-0.953,0) 2(0.953,0)
C0805H53
  rect 1.295x1.6 smd: 1(-0.953,0) 2(0.953,0)
C0805H60
  rect 1.295x1.6 smd: 1(-0.953,0) 2(0.953,0)
C1206
  rect 1.6x2.007 smd: 1(-1.397,0) 2(1.397,0)
C1206H71
  rect 1.6x2.007 smd: 1(-1.397,0) 2(1.397,0)
C3216
  rect 2.032x1.194 smd: N(1.397,0) P(-1.397,0)
CNJOHNSON142-0701-851
  rect 5.08x0.381 smd: 1(0,0)
  rect 5.08x2.413 smd: 2(0,4.381) 3(0,4.381) 4(0,-4.381) 5(0,-4.381)
CNSAMTECASP-134488-01
  round 2.54 hole 1.27 unplated: (-27.191,0) (27.191,3.048)
  round 0.635 smd: A1(-24.765,-5.715) A2(-23.495,-5.715) A3(-22.225,-5.715) A4(-20.955,-5.715) A5(-19.685,-5.715) A6(-18.415,-5.715) A7(-17.145,-5.715) A8(-15.875,-5.715) A9(-14.605,-5.715) A10(-13.335,-5.715) A11(-12.065,-5.715) A12(-10.795,-5.715) A13(-9.525,-5.715) A14(-8.255,-5.715) A15(-6.985,-5.715) A16(-5.715,-5.715) A17(-4.445,-5.715) A18(-3.175,-5.715) A19(-1.905,-5.715) A20(-0.635,-5.715) A21(0.635,-5.715) A22(1.905,-5.715) A23(3.175,-5.715) A24(4.445,-5.715) A25(5.715,-5.715) A26(6.985,-5.715) A27(8.255,-5.715) A28(9.525,-5.715) A29(10.795,-5.715) A30(12.065,-5.715) A31(13.335,-5.715) A32(14.605,-5.715) A33(15.875,-5.715) A34(17.145,-5.715) A35(18.415,-5.715) A36(19.685,-5.715) A37(20.955,-5.715) A38(22.225,-5.715) A39(23.495,-5.715) A40(24.765,-5.715) B1(-24.765,-4.445) B2(-23.495,-4.445) B3(-22.225,-4.445) B4(-20.955,-4.445) B5(-19.685,-4.445) B6(-18.415,-4.445) B7(-17.145,-4.445) B8(-15.875,-4.445) B9(-14.605,-4.445) B10(-13.335,-4.445) B11(-12.065,-4.445) B12(-10.795,-4.445) B13(-9.525,-4.445) B14(-8.255,-4.445) B15(-6.985,-4.445) B16(-5.715,-4.445) B17(-4.445,-4.445) B18(-3.175,-4.445) B19(-1.905,-4.445) B20(-0.635,-4.445) B21(0.635,-4.445) B22(1.905,-4.445) B23(3.175,-4.445) B24(4.445,-4.445) B25(5.715,-4.445) B26(6.985,-4.445) B27(8.255,-4.445) B28(9.525,-4.445) B29(10.795,-4.445) B30(12.065,-4.445) B31(13.335,-4.445) B32(14.605,-4.445) B33(15.875,-4.445) B34(17.145,-4.445) B35(18.415,-4.445) B36(19.685,-4.445) B37(20.955,-4.445) B38(22.225,-4.445) B39(23.495,-4.445) B40(24.765,-4.445) C1(-24.765,-3.175) C2(-23.495,-3.175) C3(-22.225,-3.175) C4(-20.955,-3.175) C5(-19.685,-3.175) C6(-18.415,-3.175) C7(-17.145,-3.175) C8(-15.875,-3.175) C9(-14.605,-3.175) C10(-13.335,-3.175) C11(-12.065,-3.175) C12(-10.795,-3.175) C13(-9.525,-3.175) C14(-8.255,-3.175) C15(-6.985,-3.175) C16(-5.715,-3.175) C17(-4.445,-3.175) C18(-3.175,-3.175) C19(-1.905,-3.175) C20(-0.635,-3.175) C21(0.635,-3.175) C22(1.905,-3.175) C23(3.175,-3.175) C24(4.445,-3.175) C25(5.715,-3.175) C26(6.985,-3.175) C27(8.255,-3.175) C28(9.525,-3.175) C29(10.795,-3.175) C30(12.065,-3.175) C31(13.335,-3.175) C32(14.605,-3.175) C33(15.875,-3.175) C34(17.145,-3.175) C35(18.415,-3.175) C36(19.685,-3.175) C37(20.955,-3.175) C38(22.225,-3.175) C39(23.495,-3.175) C40(24.765,-3.175) D1(-24.765,-1.905) D2(-23.495,-1.905) D3(-22.225,-1.905) D4(-20.955,-1.905) D5(-19.685,-1.905) D6(-18.415,-1.905) D7(-17.145,-1.905) D8(-15.875,-1.905) D9(-14.605,-1.905) D10(-13.335,-1.905) D11(-12.065,-1.905) D12(-10.795,-1.905) D13(-9.525,-1.905) D14(-8.255,-1.905) D15(-6.985,-1.905) D16(-5.715,-1.905) D17(-4.445,-1.905) D18(-3.175,-1.905) D19(-1.905,-1.905) D20(-0.635,-1.905) D21(0.635,-1.905) D22(1.905,-1.905) D23(3.175,-1.905) D24(4.445,-1.905) D25(5.715,-1.905) D26(6.985,-1.905) D27(8.255,-1.905) D28(9.525,-1.905) D29(10.795,-1.905) D30(12.065,-1.905) D31(13.335,-1.905) D32(14.605,-1.905) D33(15.875,-1.905) D34(17.145,-1.905) D35(18.415,-1.905) D36(19.685,-1.905) D37(20.955,-1.905) D38(22.225,-1.905) D39(23.495,-1.905) D40(24.765,-1.905) E1(-24.765,-0.635) E2(-23.495,-0.635) E3(-22.225,-0.635) E4(-20.955,-0.635) E5(-19.685,-0.635) E6(-18.415,-0.635) E7(-17.145,-0.635) E8(-15.875,-0.635) E9(-14.605,-0.635) E10(-13.335,-0.635) E11(-12.065,-0.635) E12(-10.795,-0.635) E13(-9.525,-0.635) E14(-8.255,-0.635) E15(-6.985,-0.635) E16(-5.715,-0.635) E17(-4.445,-0.635) E18(-3.175,-0.635) E19(-1.905,-0.635) E20(-0.635,-0.635) E21(0.635,-0.635) E22(1.905,-0.635) E23(3.175,-0.635) E24(4.445,-0.635) E25(5.715,-0.635) E26(6.985,-0.635) E27(8.255,-0.635) E28(9.525,-0.635) E29(10.795,-0.635) E30(12.065,-0.635) E31(13.335,-0.635) E32(14.605,-0.635) E33(15.875,-0.635) E34(17.145,-0.635) E35(18.415,-0.635) E36(19.685,-0.635) E37(20.955,-0.635) E38(22.225,-0.635) E39(23.495,-0.635) E40(24.765,-0.635) F1(-24.765,0.635) F2(-23.495,0.635) F3(-22.225,0.635) F4(-20.955,0.635) F5(-19.685,0.635) F6(-18.415,0.635) F7(-17.145,0.635) F8(-15.875,0.635) F9(-14.605,0.635) F10(-13.335,0.635) F11(-12.065,0.635) F12(-10.795,0.635) F13(-9.525,0.635) F14(-8.255,0.635) F15(-6.985,0.635) F16(-5.715,0.635) F17(-4.445,0.635) F18(-3.175,0.635) F19(-1.905,0.635) F20(-0.635,0.635) F21(0.635,0.635) F22(1.905,0.635) F23(3.175,0.635) F24(4.445,0.635) F25(5.715,0.635) F26(6.985,0.635) F27(8.255,0.635) F28(9.525,0.635) F29(10.795,0.635) F30(12.065,0.635) F31(13.335,0.635) F32(14.605,0.635) F33(15.875,0.635) F34(17.145,0.635) F35(18.415,0.635) F36(19.685,0.635) F37(20.955,0.635) F38(22.225,0.635) F39(23.495,0.635) F40(24.765,0.635) G1(-24.765,1.905) G2(-23.495,1.905) G3(-22.225,1.905) G4(-20.955,1.905) G5(-19.685,1.905) G6(-18.415,1.905) G7(-17.145,1.905) G8(-15.875,1.905) G9(-14.605,1.905) G10(-13.335,1.905) G11(-12.065,1.905) G12(-10.795,1.905) G13(-9.525,1.905) G14(-8.255,1.905) G15(-6.985,1.905) G16(-5.715,1.905) G17(-4.445,1.905) G18(-3.175,1.905) G19(-1.905,1.905) G20(-0.635,1.905) G21(0.635,1.905) G22(1.905,1.905) G23(3.175,1.905) G24(4.445,1.905) G25(5.715,1.905) G26(6.985,1.905) G27(8.255,1.905) G28(9.525,1.905) G29(10.795,1.905) G30(12.065,1.905) G31(13.335,1.905) G32(14.605,1.905) G33(15.875,1.905) G34(17.145,1.905) G35(18.415,1.905) G36(19.685,1.905) G37(20.955,1.905) G38(22.225,1.905) G39(23.495,1.905) G40(24.765,1.905) H1(-24.765,3.175) H2(-23.495,3.175) H3(-22.225,3.175) H4(-20.955,3.175) H5(-19.685,3.175) H6(-18.415,3.175) H7(-17.145,3.175) H8(-15.875,3.175) H9(-14.605,3.175) H10(-13.335,3.175) H11(-12.065,3.175) H12(-10.795,3.175) H13(-9.525,3.175) H14(-8.255,3.175) H15(-6.985,3.175) H16(-5.715,3.175) H17(-4.445,3.175) H18(-3.175,3.175) H19(-1.905,3.175) H20(-0.635,3.175) H21(0.635,3.175) H22(1.905,3.175) H23(3.175,3.175) H24(4.445,3.175) H25(5.715,3.175) H26(6.985,3.175) H27(8.255,3.175) H28(9.525,3.175) H29(10.795,3.175) H30(12.065,3.175) H31(13.335,3.175) H32(14.605,3.175) H33(15.875,3.175) H34(17.145,3.175) H35(18.415,3.175) H36(19.685,3.175) H37(20.955,3.175) H38(22.225,3.175) H39(23.495,3.175) H40(24.765,3.175) J1(-24.765,4.445) J2(-23.495,4.445) J3(-22.225,4.445) J4(-20.955,4.445) J5(-19.685,4.445) J6(-18.415,4.445) J7(-17.145,4.445) J8(-15.875,4.445) J9(-14.605,4.445) J10(-13.335,4.445) J11(-12.065,4.445) J12(-10.795,4.445) J13(-9.525,4.445) J14(-8.255,4.445) J15(-6.985,4.445) J16(-5.715,4.445) J17(-4.445,4.445) J18(-3.175,4.445) J19(-1.905,4.445) J20(-0.635,4.445) J21(0.635,4.445) J22(1.905,4.445) J23(3.175,4.445) J24(4.445,4.445) J25(5.715,4.445) J26(6.985,4.445) J27(8.255,4.445) J28(9.525,4.445) J29(10.795,4.445) J30(12.065,4.445) J31(13.335,4.445) J32(14.605,4.445) J33(15.875,4.445) J34(17.145,4.445) J35(18.415,4.445) J36(19.685,4.445) J37(20.955,4.445) J38(22.225,4.445) J39(23.495,4.445) J40(24.765,4.445) K1(-24.765,5.715) K2(-23.495,5.715) K3(-22.225,5.715) K4(-20.955,5.715) K5(-19.685,5.715) K6(-18.415,5.715) K7(-17.145,5.715) K8(-15.875,5.715) K9(-14.605,5.715) K10(-13.335,5.715) K11(-12.065,5.715) K12(-10.795,5.715) K13(-9.525,5.715) K14(-8.255,5.715) K15(-6.985,5.715) K16(-5.715,5.715) K17(-4.445,5.715) K18(-3.175,5.715) K19(-1.905,5.715) K20(-0.635,5.715) K21(0.635,5.715) K22(1.905,5.715) K23(3.175,5.715) K24(4.445,5.715) K25(5.715,5.715) K26(6.985,5.715) K27(8.255,5.715) K28(9.525,5.715) K29(10.795,5.715) K30(12.065,5.715) K31(13.335,5.715) K32(14.605,5.715) K33(15.875,5.715) K34(17.145,5.715) K35(18.415,5.715) K36(19.685,5.715) K37(20.955,5.715) K38(22.225,5.715) K39(23.495,5.715) K40(24.765,5.715)
CNSMASQ248H374
  round 1.702 smd: 1(0,0)
  rect 2.007x2.007 smd: 2(-2.502,2.502) 3(2.502,2.502) 4(2.502,-2.502) 5(-2.502,-2.502)
DFN8_3X3_PAD2_38X1_64
  oval 0.305x0.838 smd: 1(-0.75,-1.45) 2(-0.25,-1.45) 3(0.25,-1.45) 4(0.75,-1.45) 5(0.75,1.45) 6(0.25,1.45) 7(-0.25,1.45) 8(-0.75,1.45)
  rect 2.388x1.651 smd: PAD(0,0)
ETC1
  rect 0.762x1.397 smd: 1(-1.27,1.714) 2(0,1.714) 3(1.27,1.714) 4(1.27,-1.714) 5(-1.27,-1.714)
L1210H59_HS
  rect 1.092x1.803 smd: 1(-1.546,0) 2(1.546,0)
L1210H67
  rect 1.245x2.007 smd: 1(-1.272,0) 2(1.272,0)
LED0603
  rect 0.965x0.762 smd: A(0.8,0) C(-0.8,0)
LSML126W90H59
  rect 0.889x2.54 smd: 1(-1.372,0) 2(1.372,0)
LSMSQ154H47
  custom 0.362x0.362 smd: 1(-1.829,0) 2(1.829,0)
LSMSQ157H83
  rect 1.473x3.683 smd: 1(-1.232,0) 2(1.232,0)
LSMSQ157H161
  rect 0.965x3.708 smd: 1(-1.181,0) 2(1.181,0)
MINICD542
  rect 1.651x2.54 smd: 1(-2.54,-2.54) 2(0,-2.54) 3(2.54,-2.54) 4(2.54,2.54) 5(0,2.54) 6(-2.54,2.54)
MLP24_4_5X3_5_PAD3_1X2_1
  oval 0.889x0.229 smd: 1(-2.294,-0.25) 2(-2.294,-0.75) 11(2.294,-0.75) 12(2.294,-0.25) 13(2.294,0.25) 14(2.294,0.75) 23(-2.294,0.75) 24(-2.294,0.25)
  oval 0.229x0.889 smd: 3(-1.75,-1.795) 4(-1.25,-1.795) 5(-0.75,-1.795) 6(-0.25,-1.795) 7(0.25,-1.795) 8(0.75,-1.795) 9(1.25,-1.795) 10(1.75,-1.795) 15(1.75,1.795) 16(1.25,1.795) 17(0.75,1.795) 18(0.25,1.795) 19(-0.25,1.795) 20(-0.75,1.795) 21(-1.25,1.795) 22(-1.75,1.795)
  rect 3.099x2.108 smd: PAD(0,0)
PSON6
  rect 0.305x0.406 smd: 1(-0.5,-0.3) 2(0,-0.3) 3(0.5,-0.3) 4(0.5,0.3) 5(0,0.3) 6(-0.5,0.3)
QFN16_4X4_PAD2_1X2_1
  oval 0.356x1.041 smd: 1(-0.975,-1.9) 2(-0.325,-1.9) 3(0.325,-1.9) 4(0.975,-1.9) 9(0.975,1.9) 10(0.325,1.9) 11(-0.325,1.9) 12(-0.975,1.9)
  oval 1.041x0.356 smd: 5(1.9,-0.975) 6(1.9,-0.325) 7(1.9,0.325) 8(1.9,0.975) 13(-1.9,0.975) 14(-1.9,0.325) 15(-1.9,-0.325) 16(-1.9,-0.975)
  rect 2.108x2.108 smd: PAD(0,0)
QFN20_4X4_PAD2_6X2_6
  oval 0.305x1.041 smd: 1(-1,-2.019) 2(-0.5,-2.019) 3(0,-2.019) 4(0.5,-2.019) 5(1,-2.019) 11(1,2.019) 12(0.5,2.019) 13(0,2.019) 14(-0.5,2.019) 15(-1,2.019)
  oval 1.041x0.305 smd: 6(2.019,-1) 7(2.019,-0.5) 8(2.019,0) 9(2.019,0.5) 10(2.019,1) 16(-2.019,1) 17(-2.019,0.5) 18(-2.019,0) 19(-2.019,-0.5) 20(-2.019,-1)
  rect 2.591x2.591 smd: PAD(0,0)
